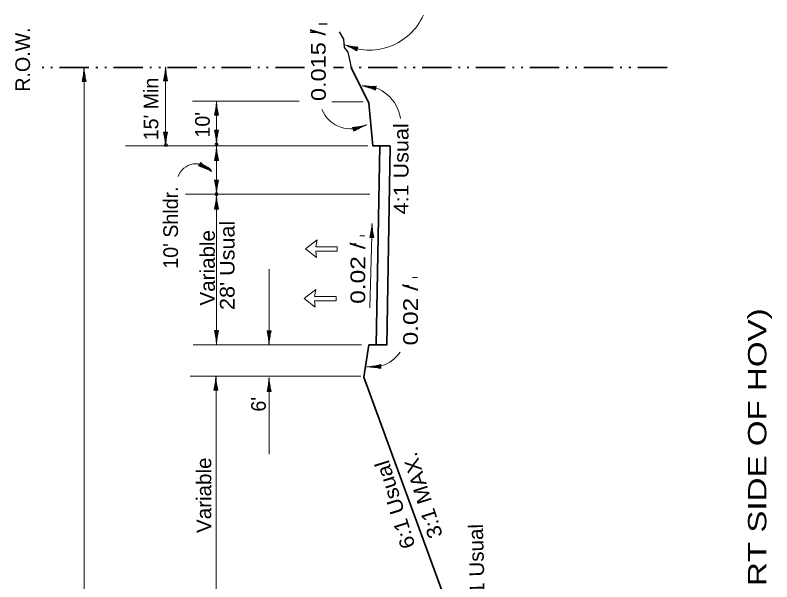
# Model space of a CAD drawing. Extents: x 2363427 to 2368559, y 6957299 to 6980140.
# Drawn here: x 2365687 to 2366410, y 6959628 to 6960169 of the extents above; entities that cross this region are included whole.
import ezdxf
from ezdxf.enums import TextEntityAlignment as Align

# ---------------------------------------------------------------- set-up
doc = ezdxf.new("R2010")
doc.units = 0
doc.header["$LTSCALE"] = 5.6
doc.header["$PDMODE"] = 32
doc.header["$PDSIZE"] = 2.8
doc.linetypes.add('DASH_DOUBLE_DOT', pattern=[9.2, 5, -1.2, 0.3, -1.2, 0.3, -1.2])
doc.linetypes.add('MEDIUM_DASHED', pattern=[4.5, 3, -1.5])
for name, color, linetype, lineweight in [('1', 7, 'Continuous', 13), ('3', 7, 'Continuous', 35), ('4', 7, 'Continuous', 13), ('40', 7, 'Continuous', 35), ('48', 7, 'Continuous', 25), ('8', 7, 'Continuous', 13)]:
    doc.layers.add(name, color=color, linetype=linetype, lineweight=lineweight)

msp = doc.modelspace()

# ---------------------------------------------------------------- linework, layer by layer
at = {"layer": '1', "linetype": 'MEDIUM_DASHED', "lineweight": 25}
msp.add_lwpolyline([(2366008.535, 6960118.496), (2366007.183, 6960124.998), (2366005.155, 6960133.668), (2366001.775, 6960138.002), (2366001.099, 6960145.95), (2365997.043, 6960153.174)], dxfattribs=at)
at = {"layer": '3', "linetype": 'DASH_DOUBLE_DOT'}
for p, q in [((2365963.671, 6960118.953), (2365711.096, 6960118.953)), ((2366309.898, 6960118.953), (2365991.186, 6960118.953))]:
    msp.add_line(p, q, dxfattribs=at)
at = {"layer": '3'}
for p, q in [((2366024.938, 6960084.964), (2366008.535, 6960118.496)), ((2366028.794, 6960044.199), (2366024.938, 6960084.964)), ((2366028.794, 6960044.199), (2366045.386, 6960044.127)), ((2366035.386, 6960044.17), (2366032.065, 6959854.135)), ((2366045.384, 6960044.061), (2366042.064, 6959854.048)), ((2366020.057, 6959823.292), (2366025.043, 6959854.136)), ((2366042.066, 6959854.135), (2366025.043, 6959854.136)), ((2366020.057, 6959823.292), (2366122.404, 6959545.045))]:
    msp.add_line(p, q, dxfattribs=at)
at = {"layer": '4', "lineweight": 25}
for p, q in [((2365985.215, 6960160.209), (2365977.054, 6960160.209)), ((2365977.085, 6960152.373), (2365968.925, 6960152.373))]:
    msp.add_line(p, q, dxfattribs=at)
at = {"layer": '4'}
for p, q in [((2366013.993, 6960136.628), (2366002.048, 6960140.522)), ((2366014.148, 6960137.103), (2366005.962, 6960139.771)), ((2366013.838, 6960136.153), (2366006.85, 6960138.431)), ((2366013.683, 6960135.677), (2366009.617, 6960137.003)), ((2366014.303, 6960137.579), (2366009.68, 6960139.085)), ((2366013.528, 6960135.201), (2366012.021, 6960135.693)), ((2366014.458, 6960138.054), (2366012.194, 6960138.792)), ((2366013.42, 6960134.869), (2366014.606, 6960138.511)), ((2365752.504, 6960105.641), (2365752.504, 6960114.251)), ((2365752.504, 6960105.641), (2365752.504, 6960114.251)), ((2365752.938, 6959093.641), (2365752.938, 6960118.953)), ((2365753.004, 6960105.641), (2365753.004, 6960118.205)), ((2365753.004, 6960105.641), (2365753.004, 6960118.205)), ((2365830.371, 6960106.284), (2365830.371, 6960114.894)), ((2365830.371, 6960106.284), (2365830.371, 6960114.894)), ((2365830.805, 6960044.06), (2365830.805, 6960119.596)), ((2365830.871, 6960106.284), (2365830.871, 6960118.848)), ((2365830.871, 6960106.284), (2365830.871, 6960118.848)), ((2365831.371, 6960106.284), (2365831.371, 6960113.634)), ((2365831.371, 6960106.284), (2365831.371, 6960113.634)), ((2365751.504, 6960105.641), (2365751.504, 6960108.023)), ((2365751.504, 6960105.641), (2365751.504, 6960108.023)), ((2365752.004, 6960105.641), (2365752.004, 6960110.503)), ((2365752.004, 6960105.641), (2365752.004, 6960110.503)), ((2365753.504, 6960105.641), (2365753.504, 6960112.991)), ((2365753.504, 6960105.641), (2365753.504, 6960112.991)), ((2365754.004, 6960105.641), (2365754.004, 6960109.917)), ((2365754.004, 6960105.641), (2365754.004, 6960109.917)), ((2365754.504, 6960105.641), (2365754.504, 6960107.226)), ((2365754.504, 6960105.641), (2365754.504, 6960107.226)), ((2365832.721, 6960106.284), (2365828.891, 6960106.284)), ((2365832.721, 6960106.284), (2365828.891, 6960106.284)), ((2365829.371, 6960106.284), (2365829.371, 6960108.666)), ((2365829.371, 6960106.284), (2365829.371, 6960108.666)), ((2365829.871, 6960106.284), (2365829.871, 6960111.146)), ((2365829.871, 6960106.284), (2365829.871, 6960111.146)), ((2365831.871, 6960106.284), (2365831.871, 6960110.56)), ((2365831.871, 6960106.284), (2365831.871, 6960110.56)), ((2365832.371, 6960106.284), (2365832.371, 6960107.869)), ((2365832.371, 6960106.284), (2365832.371, 6960107.869)), ((2365754.854, 6960105.641), (2365751.024, 6960105.641)), ((2365754.854, 6960105.641), (2365751.024, 6960105.641)), ((2366031.715, 6960099.283), (2366019.339, 6960101.448)), ((2366031.629, 6960098.789), (2366023.149, 6960100.273)), ((2366031.802, 6960099.775), (2366024.561, 6960101.042)), ((2366031.543, 6960098.297), (2366026.753, 6960099.135)), ((2366031.888, 6960100.267), (2366027.675, 6960101.005)), ((2366031.974, 6960100.759), (2366030.413, 6960101.033)), ((2366032.035, 6960101.104), (2366031.375, 6960097.332)), ((2366031.457, 6960097.805), (2366029.111, 6960098.215)), ((2365958.411, 6960086.737), (2365856.534, 6960086.737)), ((2365879.427, 6960073.34), (2365879.427, 6960085.904)), ((2365879.427, 6960073.34), (2365879.427, 6960085.904)), ((2365879.472, 6959854.504), (2365879.472, 6960086.737)), ((2366019.643, 6960086.348), (2365989.568, 6960086.348)), ((2365878.427, 6960073.34), (2365878.427, 6960077.616)), ((2365878.427, 6960073.34), (2365878.427, 6960077.616)), ((2365878.927, 6960073.34), (2365878.927, 6960080.69)), ((2365878.927, 6960073.34), (2365878.927, 6960080.69)), ((2365879.927, 6960073.34), (2365879.927, 6960081.949)), ((2365879.927, 6960073.34), (2365879.927, 6960081.949)), ((2365880.427, 6960073.34), (2365880.427, 6960078.202)), ((2365880.427, 6960073.34), (2365880.427, 6960078.202)), ((2365877.577, 6960073.34), (2365881.407, 6960073.34)), ((2365877.577, 6960073.34), (2365881.407, 6960073.34)), ((2365877.927, 6960073.34), (2365877.927, 6960074.924)), ((2365877.927, 6960073.34), (2365877.927, 6960074.924)), ((2365880.927, 6960073.34), (2365880.927, 6960075.721)), ((2365880.927, 6960073.34), (2365880.927, 6960075.721)), ((2366009.826, 6960060.49), (2366016.827, 6960062.727)), ((2366009.978, 6960060.013), (2366021.946, 6960063.837)), ((2365828.891, 6960057.372), (2365832.721, 6960057.372)), ((2365828.891, 6960057.372), (2365832.721, 6960057.372)), ((2365829.241, 6960057.372), (2365829.241, 6960055.787)), ((2365829.241, 6960057.372), (2365829.241, 6960055.787)), ((2365829.741, 6960057.372), (2365829.741, 6960053.096)), ((2365829.741, 6960057.372), (2365829.741, 6960053.096)), ((2365830.241, 6960057.372), (2365830.241, 6960050.022)), ((2365830.241, 6960057.372), (2365830.241, 6960050.022)), ((2365830.741, 6960057.372), (2365830.741, 6960044.808)), ((2365830.741, 6960057.372), (2365830.741, 6960044.808)), ((2365831.241, 6960057.372), (2365831.241, 6960048.762)), ((2365831.241, 6960057.372), (2365831.241, 6960048.762)), ((2365831.741, 6960057.372), (2365831.741, 6960052.51)), ((2365831.741, 6960057.372), (2365831.741, 6960052.51)), ((2365832.241, 6960057.372), (2365832.241, 6960054.99)), ((2365832.241, 6960057.372), (2365832.241, 6960054.99)), ((2365881.386, 6960059.147), (2365877.556, 6960059.147)), ((2365881.386, 6960059.147), (2365877.556, 6960059.147)), ((2365878.036, 6960059.147), (2365878.036, 6960056.765)), ((2365878.036, 6960059.147), (2365878.036, 6960056.765)), ((2365878.536, 6960059.147), (2365878.536, 6960054.285)), ((2365878.536, 6960059.147), (2365878.536, 6960054.285)), ((2365879.036, 6960059.147), (2365879.036, 6960050.537)), ((2365879.036, 6960059.147), (2365879.036, 6960050.537)), ((2365879.536, 6960059.147), (2365879.536, 6960046.583)), ((2365879.536, 6960059.147), (2365879.536, 6960046.583)), ((2365880.036, 6960059.147), (2365880.036, 6960051.797)), ((2365880.036, 6960059.147), (2365880.036, 6960051.797)), ((2365880.536, 6960059.147), (2365880.536, 6960054.87)), ((2365880.536, 6960059.147), (2365880.536, 6960054.87)), ((2365881.036, 6960059.147), (2365881.036, 6960057.561)), ((2365881.036, 6960059.147), (2365881.036, 6960057.561)), ((2366009.415, 6960061.776), (2366010.58, 6960058.127)), ((2366009.522, 6960061.443), (2366011.032, 6960061.925)), ((2366009.674, 6960060.966), (2366013.748, 6960062.267)), ((2366010.13, 6960059.537), (2366018.332, 6960062.157)), ((2366010.282, 6960059.061), (2366014.914, 6960060.541)), ((2366010.434, 6960058.585), (2366012.703, 6960059.309)), ((2366023.89, 6960044.264), (2365792.561, 6960044.264)), ((2365879.406, 6960030.38), (2365879.406, 6960042.944)), ((2365879.406, 6960030.38), (2365879.406, 6960042.944)), ((2365878.406, 6960030.38), (2365878.406, 6960034.656)), ((2365878.406, 6960030.38), (2365878.406, 6960034.656)), ((2365878.906, 6960030.38), (2365878.906, 6960037.73)), ((2365878.906, 6960030.38), (2365878.906, 6960037.73)), ((2365879.906, 6960030.38), (2365879.906, 6960038.989)), ((2365879.906, 6960030.38), (2365879.906, 6960038.989)), ((2365880.406, 6960030.38), (2365880.406, 6960035.242)), ((2365880.406, 6960030.38), (2365880.406, 6960035.242)), ((2365864.334, 6960028.356), (2365862.346, 6960025.082)), ((2365863.374, 6960026.775), (2365874.114, 6960020.255)), ((2365863.633, 6960027.202), (2365869.916, 6960023.388)), ((2365863.892, 6960027.629), (2365867.548, 6960025.411)), ((2365864.152, 6960028.057), (2365865.507, 6960027.234)), ((2365877.556, 6960030.38), (2365881.386, 6960030.38)), ((2365877.556, 6960030.38), (2365881.386, 6960030.38)), ((2365877.906, 6960030.38), (2365877.906, 6960031.964)), ((2365877.906, 6960030.38), (2365877.906, 6960031.964)), ((2365880.906, 6960030.38), (2365880.906, 6960032.761)), ((2365880.906, 6960030.38), (2365880.906, 6960032.761)), ((2365862.596, 6960025.493), (2365864.631, 6960024.257)), ((2365862.855, 6960025.919), (2365867.011, 6960023.397)), ((2365863.114, 6960026.347), (2365870.474, 6960021.879)), ((2365881.386, 6960011.551), (2365877.556, 6960011.551)), ((2365881.386, 6960011.551), (2365877.556, 6960011.551)), ((2365878.036, 6960011.551), (2365878.036, 6960009.169)), ((2365878.036, 6960011.551), (2365878.036, 6960009.169)), ((2365878.536, 6960011.551), (2365878.536, 6960006.689)), ((2365878.536, 6960011.551), (2365878.536, 6960006.689)), ((2365879.036, 6960011.551), (2365879.036, 6960002.941)), ((2365879.036, 6960011.551), (2365879.036, 6960002.941)), ((2365879.536, 6960011.551), (2365879.536, 6959998.987)), ((2365879.536, 6960011.551), (2365879.536, 6959998.987)), ((2365880.036, 6960011.551), (2365880.036, 6960004.201)), ((2365880.036, 6960011.551), (2365880.036, 6960004.201)), ((2365880.536, 6960011.551), (2365880.536, 6960007.274)), ((2365880.536, 6960011.551), (2365880.536, 6960007.274)), ((2365881.036, 6960011.551), (2365881.036, 6960009.965)), ((2365881.036, 6960011.551), (2365881.036, 6960009.965)), ((2366025.819, 6959998.199), (2365849.951, 6959998.199)), ((2365878.906, 6959983.902), (2365878.906, 6959991.252)), ((2365878.906, 6959983.902), (2365878.906, 6959991.252)), ((2365879.406, 6959983.902), (2365879.406, 6959996.466)), ((2365879.406, 6959983.902), (2365879.406, 6959996.466)), ((2365879.906, 6959983.902), (2365879.906, 6959992.511)), ((2365879.906, 6959983.902), (2365879.906, 6959992.511)), ((2365877.556, 6959983.902), (2365881.386, 6959983.902)), ((2365877.556, 6959983.902), (2365881.386, 6959983.902)), ((2365877.906, 6959983.902), (2365877.906, 6959985.486)), ((2365877.906, 6959983.902), (2365877.906, 6959985.486)), ((2365878.406, 6959983.902), (2365878.406, 6959988.178)), ((2365878.406, 6959983.902), (2365878.406, 6959988.178)), ((2365880.406, 6959983.902), (2365880.406, 6959988.764)), ((2365880.406, 6959983.902), (2365880.406, 6959988.764)), ((2365880.906, 6959983.902), (2365880.906, 6959986.283)), ((2365880.906, 6959983.902), (2365880.906, 6959986.283)), ((2366025.858, 6959889.69), (2366028.134, 6959969.944)), ((2366027.821, 6959956.636), (2366028.178, 6959969.194)), ((2366026.822, 6959956.664), (2366026.96, 6959961.524)), ((2366027.322, 6959956.65), (2366027.566, 6959965.256)), ((2366028.321, 6959956.622), (2366028.53, 6959963.968)), ((2366029.67, 6959956.583), (2366025.842, 6959956.692)), ((2366026.322, 6959956.678), (2366026.39, 6959959.058)), ((2366028.821, 6959956.607), (2366028.942, 6959960.882)), ((2366029.32, 6959956.593), (2366029.366, 6959958.178)), ((2365929.672, 6959854.264), (2365929.672, 6959926.525)), ((2365881.386, 6959867.816), (2365877.556, 6959867.816)), ((2365881.386, 6959867.816), (2365877.556, 6959867.816)), ((2365878.036, 6959867.816), (2365878.036, 6959865.434)), ((2365878.036, 6959867.816), (2365878.036, 6959865.434)), ((2365878.536, 6959867.816), (2365878.536, 6959862.954)), ((2365878.536, 6959867.816), (2365878.536, 6959862.954)), ((2365879.036, 6959867.816), (2365879.036, 6959859.206)), ((2365879.036, 6959867.816), (2365879.036, 6959859.206)), ((2365879.536, 6959867.816), (2365879.536, 6959855.252)), ((2365879.536, 6959867.816), (2365879.536, 6959855.252)), ((2365880.036, 6959867.816), (2365880.036, 6959860.466)), ((2365880.036, 6959867.816), (2365880.036, 6959860.466)), ((2365880.536, 6959867.816), (2365880.536, 6959863.539)), ((2365880.536, 6959867.816), (2365880.536, 6959863.539)), ((2365881.036, 6959867.816), (2365881.036, 6959866.23)), ((2365881.036, 6959867.816), (2365881.036, 6959866.23)), ((2365927.758, 6959867.575), (2365931.588, 6959867.575)), ((2365927.758, 6959867.575), (2365931.588, 6959867.575)), ((2365928.108, 6959867.575), (2365928.108, 6959865.991)), ((2365928.108, 6959867.575), (2365928.108, 6959865.991)), ((2365928.608, 6959867.575), (2365928.608, 6959863.299)), ((2365928.608, 6959867.575), (2365928.608, 6959863.299)), ((2365929.108, 6959867.575), (2365929.108, 6959860.225)), ((2365929.108, 6959867.575), (2365929.108, 6959860.225)), ((2365929.608, 6959867.575), (2365929.608, 6959855.011)), ((2365929.608, 6959867.575), (2365929.608, 6959855.011)), ((2365930.108, 6959867.575), (2365930.108, 6959858.966)), ((2365930.108, 6959867.575), (2365930.108, 6959858.966)), ((2365930.608, 6959867.575), (2365930.608, 6959862.713)), ((2365930.608, 6959867.575), (2365930.608, 6959862.713)), ((2365931.108, 6959867.575), (2365931.108, 6959865.194)), ((2365931.108, 6959867.575), (2365931.108, 6959865.194)), ((2366018.06, 6959854.264), (2365857.076, 6959854.264)), ((2366036.429, 6959833.652), (2366023.869, 6959833.324)), ((2366036.442, 6959833.152), (2366027.834, 6959832.927)), ((2366036.416, 6959834.151), (2366029.068, 6959833.96)), ((2366036.455, 6959832.652), (2366031.594, 6959832.525)), ((2366036.402, 6959834.651), (2366032.128, 6959834.54)), ((2366036.467, 6959832.151), (2366034.087, 6959832.09)), ((2366036.389, 6959835.151), (2366034.805, 6959835.109)), ((2366036.38, 6959835.5), (2366036.48, 6959831.672)), ((2366017.439, 6959824.364), (2365854.255, 6959824.364)), ((2365879.004, 6959590.203), (2365879.074, 6959824.364)), ((2365878.362, 6959810.897), (2365878.365, 6959819.507)), ((2365878.362, 6959810.897), (2365878.365, 6959819.507)), ((2365878.862, 6959810.897), (2365878.866, 6959823.461)), ((2365878.862, 6959810.897), (2365878.866, 6959823.461)), ((2365879.362, 6959810.897), (2365879.365, 6959818.246)), ((2365879.362, 6959810.897), (2365879.365, 6959818.246)), ((2365929.238, 6959809.812), (2365929.238, 6959818.421)), ((2365929.672, 6959749.864), (2365929.672, 6959823.123)), ((2365929.738, 6959809.812), (2365929.738, 6959822.376)), ((2365930.238, 6959809.812), (2365930.238, 6959817.162)), ((2365880.712, 6959810.896), (2365876.882, 6959810.897)), ((2365880.712, 6959810.896), (2365876.882, 6959810.897)), ((2365877.362, 6959810.897), (2365877.364, 6959813.279)), ((2365877.362, 6959810.897), (2365877.364, 6959813.279)), ((2365877.862, 6959810.897), (2365877.864, 6959815.759)), ((2365877.862, 6959810.897), (2365877.864, 6959815.759)), ((2365879.862, 6959810.896), (2365879.864, 6959815.173)), ((2365879.862, 6959810.896), (2365879.864, 6959815.173)), ((2365880.362, 6959810.896), (2365880.363, 6959812.481)), ((2365880.362, 6959810.896), (2365880.363, 6959812.481)), ((2365931.588, 6959809.812), (2365927.758, 6959809.812)), ((2365928.238, 6959809.812), (2365928.238, 6959812.193)), ((2365928.738, 6959809.812), (2365928.738, 6959814.674)), ((2365930.738, 6959809.812), (2365930.738, 6959814.088)), ((2365931.238, 6959809.812), (2365931.238, 6959811.396))]:
    msp.add_line(p, q, dxfattribs=at)
for centre, radius, start, end in [((2366025.258, 6960192.316), 56.809, 245.09051, 335.73339), ((2366020.305, 6960210.498), 72.212, 254.78783, 265.47388), ((2365975.597, 6960073.354), 72.212, 58.41466, 69.10071), ((2365680.815, 6960122.535), 72.212, 346.47039, 357.15644), ((2365680.815, 6960122.535), 72.212, 346.47039, 357.15644), ((2365825.062, 6960122.535), 72.212, 182.84356, 193.52961), ((2365825.062, 6960122.535), 72.212, 182.84356, 193.52961), ((2365758.682, 6960123.178), 72.212, 346.47039, 357.15644), ((2365758.682, 6960123.178), 72.212, 346.47039, 357.15644), ((2365902.929, 6960123.178), 72.212, 182.84356, 193.52961), ((2365902.929, 6960123.178), 72.212, 182.84356, 193.52961), ((2366002.63, 6960031.087), 72.212, 66.5439, 77.22995), ((2366027.496, 6960173.174), 72.212, 262.91707, 273.60312), ((2366019.389, 6960065.61), 36.023, 7.28739, 91.11463), ((2365807.369, 6960090.234), 72.212, 346.47039, 357.15644), ((2365807.369, 6960090.234), 72.212, 346.47039, 357.15644), ((2365951.616, 6960090.234), 72.212, 182.84356, 193.52961), ((2365951.616, 6960090.234), 72.212, 182.84356, 193.52961), ((2366007.658, 6960090.066), 29.635, 202.18381, 300.37926), ((2366004.142, 6960133.797), 72.212, 274.18736, 284.87341), ((2366048.039, 6959996.391), 72.212, 110.56052, 121.24657), ((2365758.682, 6960040.478), 72.212, 2.84356, 13.52961), ((2365758.682, 6960040.478), 72.212, 2.84356, 13.52961), ((2365902.929, 6960040.478), 72.212, 166.47039, 177.15644), ((2365902.929, 6960040.478), 72.212, 166.47039, 177.15644), ((2365807.348, 6960042.253), 72.212, 2.84356, 13.52961), ((2365807.348, 6960042.253), 72.212, 2.84356, 13.52961), ((2365951.595, 6960042.253), 72.212, 166.47039, 177.15644), ((2365951.595, 6960042.253), 72.212, 166.47039, 177.15644), ((2365807.348, 6960047.274), 72.212, 346.47039, 357.15644), ((2365807.348, 6960047.274), 72.212, 346.47039, 357.15644), ((2365951.595, 6960047.274), 72.212, 182.84356, 193.52961), ((2365951.595, 6960047.274), 72.212, 182.84356, 193.52961), ((2365860.341, 6960008.355), 18.823, 40.25616, 159.15022), ((2365915.208, 6960079.605), 72.212, 225.21017, 235.89622), ((2365840.355, 6959956.3), 72.212, 61.58334, 72.26939), ((2365807.348, 6959994.657), 72.212, 2.84356, 13.52961), ((2365807.348, 6959994.657), 72.212, 2.84356, 13.52961), ((2365951.595, 6959994.657), 72.212, 166.47039, 177.15644), ((2365951.595, 6959994.657), 72.212, 166.47039, 177.15644), ((2365807.348, 6960000.796), 72.212, 346.47039, 357.15644), ((2365807.348, 6960000.796), 72.212, 346.47039, 357.15644), ((2365951.595, 6960000.796), 72.212, 182.84356, 193.52961), ((2365951.595, 6960000.796), 72.212, 182.84356, 193.52961), ((2365956.14, 6959975.569), 72.212, 344.84626, 355.53231), ((2366100.329, 6959971.48), 72.212, 181.21943, 191.90548), ((2365807.348, 6959850.922), 72.212, 2.84356, 13.52961), ((2365807.348, 6959850.922), 72.212, 2.84356, 13.52961), ((2365951.595, 6959850.922), 72.212, 166.47039, 177.15644), ((2365951.595, 6959850.922), 72.212, 166.47039, 177.15644), ((2365857.549, 6959850.682), 72.212, 2.84356, 13.52961), ((2365857.549, 6959850.682), 72.212, 2.84356, 13.52961), ((2366001.796, 6959850.682), 72.212, 166.47039, 177.15644), ((2366001.796, 6959850.682), 72.212, 166.47039, 177.15644), ((2366028.347, 6959864.785), 31.768, 260.35981, 326.74144), ((2366017.66, 6959905.244), 72.212, 274.33889, 285.02494), ((2366021.424, 6959761.047), 72.212, 77.96572, 88.65177), ((2365806.679, 6959827.812), 72.212, 346.45333, 357.13938), ((2365806.679, 6959827.812), 72.212, 346.45333, 357.13938), ((2365950.926, 6959827.769), 72.212, 182.82649, 193.51254), ((2365950.926, 6959827.769), 72.212, 182.82649, 193.51254), ((2365857.549, 6959826.705), 72.212, 346.47039, 357.15644), ((2366001.796, 6959826.705), 72.212, 182.84356, 193.52961)]:
    msp.add_arc(centre, radius, start, end, dxfattribs=at)
for p in [(2365831.203, 6960044.959), (2365879.472, 6960045.835), (2365879.472, 6960045.434), (2365879.472, 6959998.239), (2365879.472, 6959997.838), (2365879.472, 6959985.417)]:
    msp.add_point(p, dxfattribs=at)
at = {"layer": '40', "lineweight": 13}
for p, q in [((2365974.33, 6959943.799), (2365994.836, 6959943.604)), ((2365973.145, 6959896.406), (2365993.65, 6959896.211))]:
    msp.add_line(p, q, dxfattribs=at)
for points in [[(2365974.33, 6959943.799), (2365974.863, 6959937.484), (2365964.476, 6959946.019), (2365975.576, 6959954.621), (2365974.368, 6959947.894)], [(2365974.368, 6959947.894), (2365994.873, 6959947.699), (2365994.836, 6959943.604)], [(2365973.145, 6959896.406), (2365973.678, 6959890.091), (2365963.29, 6959898.626), (2365974.39, 6959907.229), (2365973.182, 6959900.501)], [(2365973.182, 6959900.501), (2365993.688, 6959900.306), (2365993.65, 6959896.211)]]:
    msp.add_lwpolyline(points, dxfattribs=at)
at = {"layer": '48', "lineweight": 13}
for p, q in [((2366016.421, 6959958.214), (2366021.191, 6959958.214)), ((2366012.923, 6959950.588), (2366007.2, 6959950.588)), ((2366066.739, 6959918.481), (2366071.509, 6959918.481)), ((2366063.242, 6959910.854), (2366057.518, 6959910.854))]:
    msp.add_line(p, q, dxfattribs=at)
msp.add_lwpolyline([(2366032.065, 6959854.135), (2366042.064, 6959854.048), (2366045.384, 6960044.061), (2366035.386, 6960044.17)], close=True, dxfattribs=at)
at = {"layer": '8'}
for points in [[(2365964.476, 6959946.019), (2365974.863, 6959937.484), (2365974.33, 6959943.799), (2365994.836, 6959943.604), (2365994.873, 6959947.699), (2365974.368, 6959947.894), (2365975.576, 6959954.621)], [(2365963.29, 6959898.626), (2365973.678, 6959890.091), (2365973.145, 6959896.406), (2365993.65, 6959896.211), (2365993.688, 6959900.306), (2365973.182, 6959900.501), (2365974.39, 6959907.229)]]:
    msp.add_lwpolyline(points, close=True, dxfattribs=at)

# ---------------------------------------------------------------- texts
at = {"layer": '4'}
for s, p in [('R.O.W.', (2365701.308, 6960126.606)), ("15' Min", (2365823.837, 6960079.394)), ("10' ", (2365873.041, 6960066.937)), ("10' Shldr.", (2365842.659, 6959966.217)), ("6' ", (2365926.562, 6959800.145))]:
    msp.add_text(s, height=14, rotation=90, dxfattribs=at).set_placement(p, align=Align.CENTER)
for s, height, rotation, width, p in [('0.015 /', 14, 90.292, 1.2, (2365983.764, 6960121.344)), ('4:1 Usual', 14, 89.994, 1.1, (2366062.846, 6960022.22)), ("28' Usual", 14, 90, 1.1, (2365896.674, 6959930.125)), ('Variable', 14, 90, 1.05, (2365877.833, 6959927.819)), ('0.02 /', 14, 90, 1.25, (2366021.478, 6959922.694)), ('0.02 /', 14, 90, 1.25, (2366071.796, 6959882.961)), ('(RETAINING WALL ON LT & RT SIDE OF HOV)', 17.5, 90, 1.35, (2366404.708, 6959547.735)), ('Variable', 14, 90, 1.05, (2365874.412, 6959710.678)), ('3:1 MAX.', 14, 107.484, 1.1, (2366082.997, 6959712.661)), ('6:1 Usual', 14, 107.36, 1.1, (2366056.644, 6959703.812)), ('6:1 Usual', 14, 91.404, 1.05, (2366134.955, 6959641.906))]:
    msp.add_text(s, height=height, rotation=rotation, dxfattribs=dict(at, width=width)).set_placement(p, align=Align.CENTER)

doc.saveas('drawing.dxf')
